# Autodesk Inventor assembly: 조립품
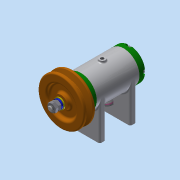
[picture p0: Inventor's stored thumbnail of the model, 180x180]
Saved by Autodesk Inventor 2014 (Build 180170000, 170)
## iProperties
Created: 2020-07
Part Number: 조립품
Document SubType Name: Assembly
Designer: kh
Author: kh
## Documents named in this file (15)
- C:\Users\kh\Desktop\700706V1022\조립품.iam
- C:\Users\kh\Desktop\700706V1022\본체.ipt
- C:\Users\kh\Desktop\700706V1022\베어링 6002.ipt
- C:\Users\kh\Desktop\700706V1022\뒤커버.ipt
- C:\Users\kh\Desktop\700706V1022\앞커버.ipt
- C:\Users\kh\Desktop\700706V1022\축.ipt
- C:\Users\kh\Desktop\700706V1022\키 3x3x12.ipt
- C:\Users\kh\Desktop\700706V1022\오일 실 15 25 7.ipt
- C:\Users\kh\Desktop\700706V1022\V벨트풀리.ipt
- C:\Users\kh\Desktop\700706V1022\와셔 8x17.ipt
- C:\Users\kh\Desktop\700706V1022\스프링와셔 8.ipt
- C:\Users\kh\Desktop\700706V1022\너트 M8.ipt
- C:\Users\kh\Desktop\700706V1022\와셔 6x11.5.ipt
- C:\Users\kh\Desktop\700706V1022\볼트 M6x8.ipt
- C:\Users\kh\Desktop\700706V1022\볼트 M4x12.ipt
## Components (1 placed, 1 different names)
1. V벨트풀리:1 — Insert:4
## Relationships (1: Insert 1)
- Insert:4: V벨트풀리:1
